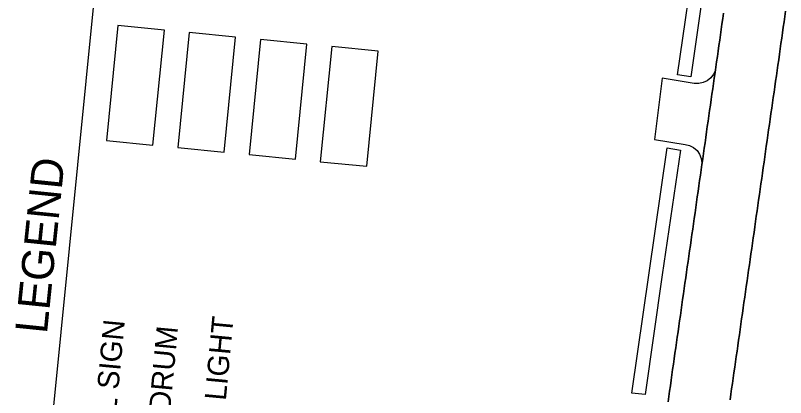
# Model space of a CAD drawing. Extents: x 1795987 to 1799689, y 243690 to 251545.
# Drawn here: x 1797261.2 to 1797542.5, y 247313.4 to 247453.1 of the extents above; entities that cross this region are included whole.
import ezdxf

# ---------------------------------------------------------------- set-up
doc = ezdxf.new("R2010")
doc.units = 0
for name, color, linetype in [('EP', 7, 'Continuous'), ('LEGEND', 7, 'Continuous'), ('Level 2', 7, 'Continuous'), ('Level 62', 7, 'Continuous'), ('Phase 2 Hatching', 7, 'Continuous')]:
    doc.layers.add(name, color=color, linetype=linetype)

msp = doc.modelspace()

# ---------------------------------------------------------------- linework, layer by layer
at = {"layer": 'EP'}
for p, q in [((1797507.92, 247430.67), (1797502.98, 247431.42)), ((1797499.19, 247404.72), (1797504.07, 247403.85)), ((1797491.2, 247314.5), (1797486.32, 247315.04))]:
    msp.add_line(p, q, dxfattribs=at)
for points in [[(1797502.98, 247431.42), (1797509.89, 247479.28), (1797512.41, 247496.92), (1797513.21, 247499.92), (1797514.39, 247502.79), (1797515.55, 247504.9), (1797517.77, 247509.13), (1797519.86, 247513.31), (1797520.78, 247515.42), (1797521.93, 247518.67), (1797522.28, 247519.96), (1797522.83, 247522.6), (1797523.1, 247524.61), (1797523.26, 247527.63), (1797523.1, 247531.02), (1797522.82, 247533.27), (1797521.91, 247537.81), (1797521.35, 247540.15), (1797520.54, 247543.7), (1797520.12, 247547.31), (1797520.09, 247550.71), (1797523.74, 247576.05), (1797530.2, 247621.54), (1797536.99, 247668.47)], [(1797541.84, 247667.67), (1797535.11, 247620.83), (1797528.62, 247575.39), (1797524.96, 247549.93), (1797525.06, 247548.02), (1797525.55, 247543.91), (1797526.45, 247539.86), (1797526.65, 247538.96), (1797527.41, 247535.59), (1797527.98, 247531.38), (1797528.16, 247527.13), (1797526.97, 247518.48), (1797526.28, 247516.25), (1797524.64, 247511.95), (1797522.63, 247507.8), (1797522.17, 247506.93), (1797521.53, 247505.59), (1797517.43, 247496.48), (1797514.72, 247478.52), (1797507.92, 247430.67)], [(1797486.32, 247315.04), (1797492.66, 247359.05), (1797499.19, 247404.72)], [(1797504.07, 247403.85), (1797497.45, 247358.32), (1797491.2, 247314.5)]]:
    msp.add_lwpolyline(points, dxfattribs=at)
at = {"layer": 'LEGEND'}
msp.add_line((1797261.35, 247170.53), (1797308.29, 247644.28), dxfattribs=at)
for points in [[(1797311.42, 247405.67), (1797315.58, 247447.74), (1797298.6, 247449.42), (1797294.43, 247407.35)], [(1797337.45, 247403.09), (1797341.62, 247445.16), (1797324.63, 247446.84), (1797320.46, 247404.77)], [(1797363.49, 247400.51), (1797367.66, 247442.58), (1797350.67, 247444.26), (1797346.5, 247402.19)], [(1797389.53, 247397.93), (1797393.69, 247440), (1797376.71, 247441.68), (1797372.54, 247399.61)]]:
    msp.add_lwpolyline(points, close=True, dxfattribs=at)
at = {"layer": 'Level 2'}
msp.add_lwpolyline([(1797389.53, 247397.93), (1797393.69, 247440), (1797376.71, 247441.68), (1797372.54, 247399.61)], close=True, dxfattribs=at)
at = {"layer": 'Level 62'}
for points in [[(1797542.49, 247454.65), (1797542.21, 247452.67), (1797541.93, 247450.7), (1797541.65, 247448.73), (1797541.36, 247446.76), (1797541.08, 247444.78), (1797540.8, 247442.81), (1797540.52, 247440.84), (1797540.24, 247438.87), (1797539.96, 247436.89), (1797539.67, 247434.92), (1797539.39, 247432.95), (1797539.11, 247430.98), (1797538.83, 247429), (1797538.55, 247427.03), (1797538.27, 247425.06), (1797537.99, 247423.09), (1797537.7, 247421.11), (1797537.42, 247419.14), (1797537.14, 247417.17), (1797536.86, 247415.2), (1797536.58, 247413.22), (1797536.3, 247411.25), (1797536.01, 247409.28), (1797535.73, 247407.31), (1797535.45, 247405.33), (1797535.17, 247403.36), (1797534.89, 247401.39), (1797534.61, 247399.42), (1797534.32, 247397.44), (1797534.04, 247395.47), (1797533.76, 247393.5), (1797533.48, 247391.53), (1797533.2, 247389.56), (1797532.92, 247387.58), (1797532.64, 247385.61), (1797532.35, 247383.64), (1797532.07, 247381.67), (1797531.79, 247379.69), (1797531.51, 247377.72), (1797531.23, 247375.75), (1797530.95, 247373.78), (1797530.66, 247371.8), (1797530.38, 247369.83), (1797530.1, 247367.86), (1797529.82, 247365.89), (1797529.54, 247363.91), (1797529.26, 247361.94), (1797528.98, 247359.97), (1797528.69, 247358), (1797528.41, 247356.02), (1797528.13, 247354.05), (1797527.85, 247352.08), (1797527.57, 247350.11), (1797527.29, 247348.13), (1797527, 247346.16), (1797526.72, 247344.19), (1797526.44, 247342.22), (1797526.16, 247340.24), (1797525.88, 247338.27), (1797525.6, 247336.3), (1797525.31, 247334.33), (1797525.03, 247332.35), (1797524.75, 247330.38), (1797524.47, 247328.41), (1797524.19, 247326.44), (1797523.91, 247324.46), (1797523.63, 247322.49), (1797523.34, 247320.52), (1797523.06, 247318.55), (1797522.78, 247316.57), (1797522.5, 247314.6), (1797522.22, 247312.63)], [(1797522.22, 247312.63), (1797522.5, 247314.6), (1797522.78, 247316.57), (1797523.06, 247318.55), (1797523.34, 247320.52), (1797523.63, 247322.49), (1797523.91, 247324.46), (1797524.19, 247326.44), (1797524.47, 247328.41), (1797524.75, 247330.38), (1797525.03, 247332.35), (1797525.31, 247334.33), (1797525.6, 247336.3), (1797525.88, 247338.27), (1797526.16, 247340.24), (1797526.44, 247342.22), (1797526.72, 247344.19), (1797527, 247346.16), (1797527.29, 247348.13), (1797527.57, 247350.11), (1797527.85, 247352.08), (1797528.13, 247354.05), (1797528.41, 247356.02), (1797528.69, 247358), (1797528.98, 247359.97), (1797529.26, 247361.94), (1797529.54, 247363.91), (1797529.82, 247365.89), (1797530.1, 247367.86), (1797530.38, 247369.83), (1797530.66, 247371.8), (1797530.95, 247373.78), (1797531.23, 247375.75), (1797531.51, 247377.72), (1797531.79, 247379.69), (1797532.07, 247381.67), (1797532.35, 247383.64), (1797532.64, 247385.61), (1797532.92, 247387.58), (1797533.2, 247389.56), (1797533.48, 247391.53), (1797533.76, 247393.5), (1797534.04, 247395.47), (1797534.32, 247397.44), (1797534.61, 247399.42), (1797534.89, 247401.39), (1797535.17, 247403.36), (1797535.45, 247405.33), (1797535.73, 247407.31), (1797536.01, 247409.28), (1797536.3, 247411.25), (1797536.58, 247413.22), (1797536.86, 247415.2), (1797537.14, 247417.17), (1797537.42, 247419.14), (1797537.7, 247421.11), (1797537.99, 247423.09), (1797538.27, 247425.06), (1797538.55, 247427.03), (1797538.83, 247429), (1797539.11, 247430.98), (1797539.39, 247432.95), (1797539.67, 247434.92), (1797539.96, 247436.89), (1797540.24, 247438.87), (1797540.52, 247440.84), (1797540.8, 247442.81), (1797541.08, 247444.78), (1797541.36, 247446.76), (1797541.65, 247448.73), (1797541.93, 247450.7), (1797542.21, 247452.67), (1797542.49, 247454.65)], [(1797499.54, 247311.83), (1797499.82, 247313.8), (1797500.11, 247315.78), (1797500.39, 247317.75), (1797500.67, 247319.72), (1797500.95, 247321.7), (1797501.23, 247323.67), (1797501.51, 247325.64), (1797501.8, 247327.61), (1797502.08, 247329.59), (1797502.36, 247331.56), (1797502.64, 247333.53), (1797502.92, 247335.5), (1797503.2, 247337.48), (1797503.48, 247339.45), (1797503.77, 247341.42), (1797504.05, 247343.39), (1797504.33, 247345.37), (1797504.61, 247347.34), (1797504.89, 247349.31), (1797505.17, 247351.29), (1797505.46, 247353.26), (1797505.74, 247355.23), (1797506.02, 247357.2), (1797506.3, 247359.18), (1797506.58, 247361.15), (1797506.86, 247363.12), (1797507.15, 247365.09), (1797507.43, 247367.07), (1797507.71, 247369.04), (1797507.99, 247371.01), (1797508.27, 247372.99), (1797508.55, 247374.96), (1797508.84, 247376.93), (1797509.12, 247378.9), (1797509.4, 247380.88), (1797509.68, 247382.85), (1797509.96, 247384.82), (1797510.24, 247386.79), (1797510.52, 247388.77), (1797510.81, 247390.74), (1797511.09, 247392.71), (1797511.37, 247394.69), (1797511.65, 247396.66), (1797511.93, 247398.63), (1797512.21, 247400.6), (1797512.5, 247402.58), (1797512.78, 247404.55), (1797513.06, 247406.52), (1797513.34, 247408.49), (1797513.62, 247410.47), (1797513.9, 247412.44), (1797514.19, 247414.41), (1797514.47, 247416.39), (1797514.75, 247418.36), (1797515.03, 247420.33), (1797515.31, 247422.3), (1797515.59, 247424.28), (1797515.88, 247426.25), (1797516.16, 247428.22), (1797516.44, 247430.19), (1797516.72, 247432.17), (1797517, 247434.14), (1797517.28, 247436.11), (1797517.57, 247438.09), (1797517.85, 247440.06), (1797518.13, 247442.03), (1797518.41, 247444), (1797518.69, 247445.98), (1797518.97, 247447.95), (1797519.25, 247449.92), (1797519.54, 247451.89), (1797519.82, 247453.87)], [(1797519.82, 247453.87), (1797519.54, 247451.89), (1797519.25, 247449.92), (1797518.97, 247447.95), (1797518.69, 247445.98), (1797518.41, 247444), (1797518.13, 247442.03), (1797517.85, 247440.06), (1797517.57, 247438.09), (1797517.28, 247436.11), (1797517, 247434.14), (1797516.72, 247432.17), (1797516.44, 247430.19), (1797516.16, 247428.22), (1797515.88, 247426.25), (1797515.59, 247424.28), (1797515.31, 247422.3), (1797515.03, 247420.33), (1797514.75, 247418.36), (1797514.47, 247416.39), (1797514.19, 247414.41), (1797513.9, 247412.44), (1797513.62, 247410.47), (1797513.34, 247408.49), (1797513.06, 247406.52), (1797512.78, 247404.55), (1797512.5, 247402.58), (1797512.21, 247400.6), (1797511.93, 247398.63), (1797511.65, 247396.66), (1797511.37, 247394.69), (1797511.09, 247392.71), (1797510.81, 247390.74), (1797510.52, 247388.77), (1797510.24, 247386.79), (1797509.96, 247384.82), (1797509.68, 247382.85), (1797509.4, 247380.88), (1797509.12, 247378.9), (1797508.84, 247376.93), (1797508.55, 247374.96), (1797508.27, 247372.99), (1797507.99, 247371.01), (1797507.71, 247369.04), (1797507.43, 247367.07), (1797507.15, 247365.09), (1797506.86, 247363.12), (1797506.58, 247361.15), (1797506.3, 247359.18), (1797506.02, 247357.2), (1797505.74, 247355.23), (1797505.46, 247353.26), (1797505.17, 247351.29), (1797504.89, 247349.31), (1797504.61, 247347.34), (1797504.33, 247345.37), (1797504.05, 247343.39), (1797503.77, 247341.42), (1797503.48, 247339.45), (1797503.2, 247337.48), (1797502.92, 247335.5), (1797502.64, 247333.53), (1797502.36, 247331.56), (1797502.08, 247329.59), (1797501.8, 247327.61), (1797501.51, 247325.64), (1797501.23, 247323.67), (1797500.95, 247321.7), (1797500.67, 247319.72), (1797500.39, 247317.75), (1797500.11, 247315.78), (1797499.82, 247313.8), (1797499.54, 247311.83)], [(1797346.5, 247402.19), (1797363.49, 247400.51), (1797367.66, 247442.58), (1797350.67, 247444.26), (1797346.5, 247402.19)], [(1797516.85, 247433.11), (1797516.85, 247433.11), (1797516.19, 247431.59), (1797515.19, 247430.26), (1797513.9, 247429.22), (1797512.4, 247428.51), (1797510.78, 247428.18), (1797509.12, 247428.24), (1797497.35, 247430.15), (1797494.65, 247407.73), (1797505.83, 247405.84), (1797507.43, 247405.49), (1797508.89, 247404.75), (1797510.13, 247403.69), (1797511.08, 247402.36), (1797511.67, 247400.84), (1797511.88, 247399.22), (1797511.69, 247397.59), (1797511.78, 247397.58), (1797511.93, 247398.63), (1797512.21, 247400.6), (1797512.5, 247402.58), (1797512.78, 247404.55), (1797513.06, 247406.52), (1797513.34, 247408.49), (1797513.62, 247410.47), (1797513.9, 247412.44), (1797514.19, 247414.41), (1797514.47, 247416.39), (1797514.75, 247418.36), (1797515.03, 247420.33), (1797515.31, 247422.3), (1797515.59, 247424.28), (1797515.88, 247426.25), (1797516.16, 247428.22), (1797516.44, 247430.19), (1797516.72, 247432.17), (1797516.85, 247433.11)]]:
    msp.add_lwpolyline(points, dxfattribs=at)
at = {"layer": 'Phase 2 Hatching'}
msp.add_lwpolyline([(1797389.53, 247397.93), (1797393.69, 247440), (1797376.71, 247441.68), (1797372.54, 247399.61)], close=True, dxfattribs=at)

# ---------------------------------------------------------------- texts
at = {"layer": 'LEGEND'}
for s, height, rotation, p in [('LEGEND', 11.7, 84.1754, (1797272.68, 247336.47)), ('TYPE "B" WARNING LIGHT', 7.7999, 84.6544, (1797328.64, 247211.85)), ('TRAFFIC CONTROL SIGN', 7.7999, 84.6544, (1797289.39, 247215.75)), ('CHANNELIZATION DRUM', 7.7999, 84.6544, (1797308.94, 247214.55))]:
    msp.add_text(s, height=height, rotation=rotation, dxfattribs=at).set_placement(p)

doc.saveas('drawing.dxf')
